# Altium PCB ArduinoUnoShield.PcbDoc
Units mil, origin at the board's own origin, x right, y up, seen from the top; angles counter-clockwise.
Board outline 2700 x 2100 mil, 2 copper layers (Top Layer, Bottom Layer); 5 components, 32 nets, 42 pads, 0 vias.
Unrouted connection lines stored in the file: 5.
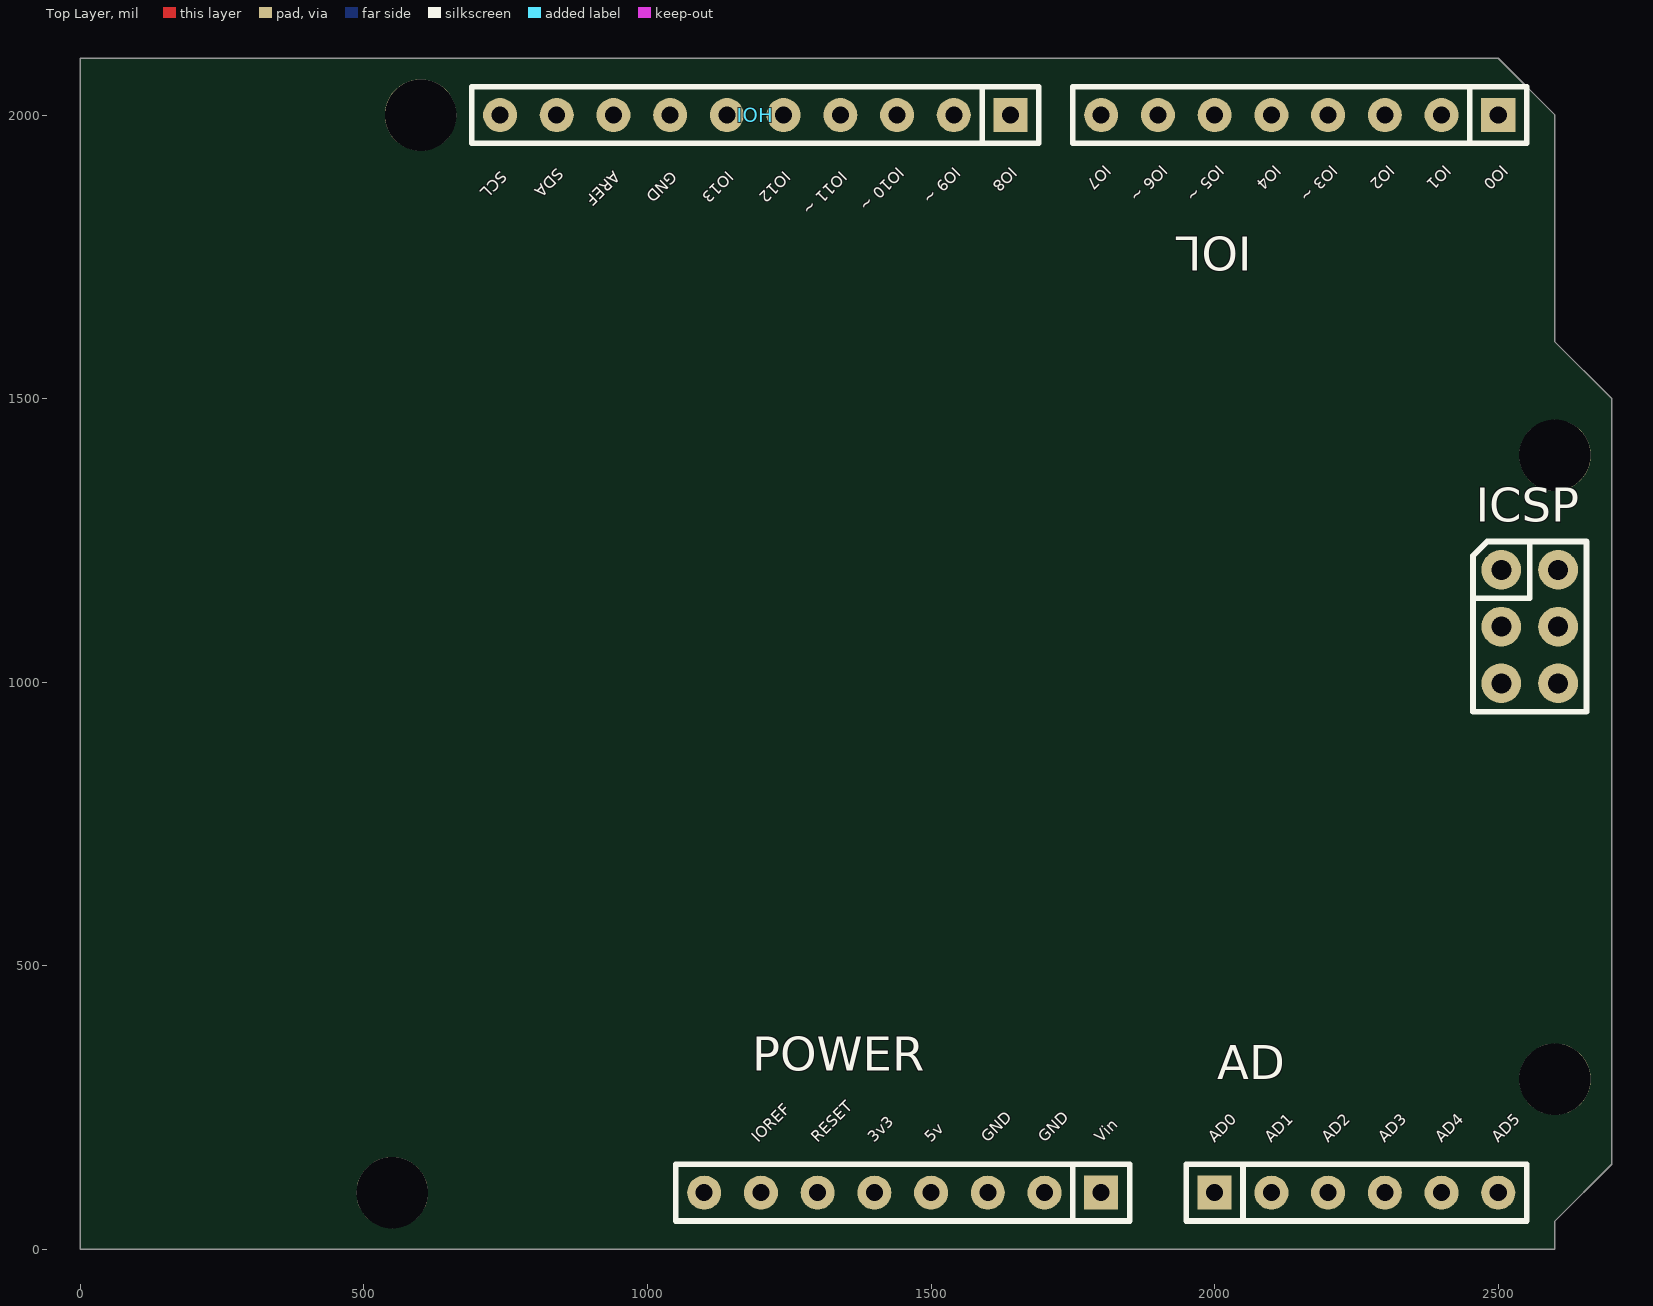
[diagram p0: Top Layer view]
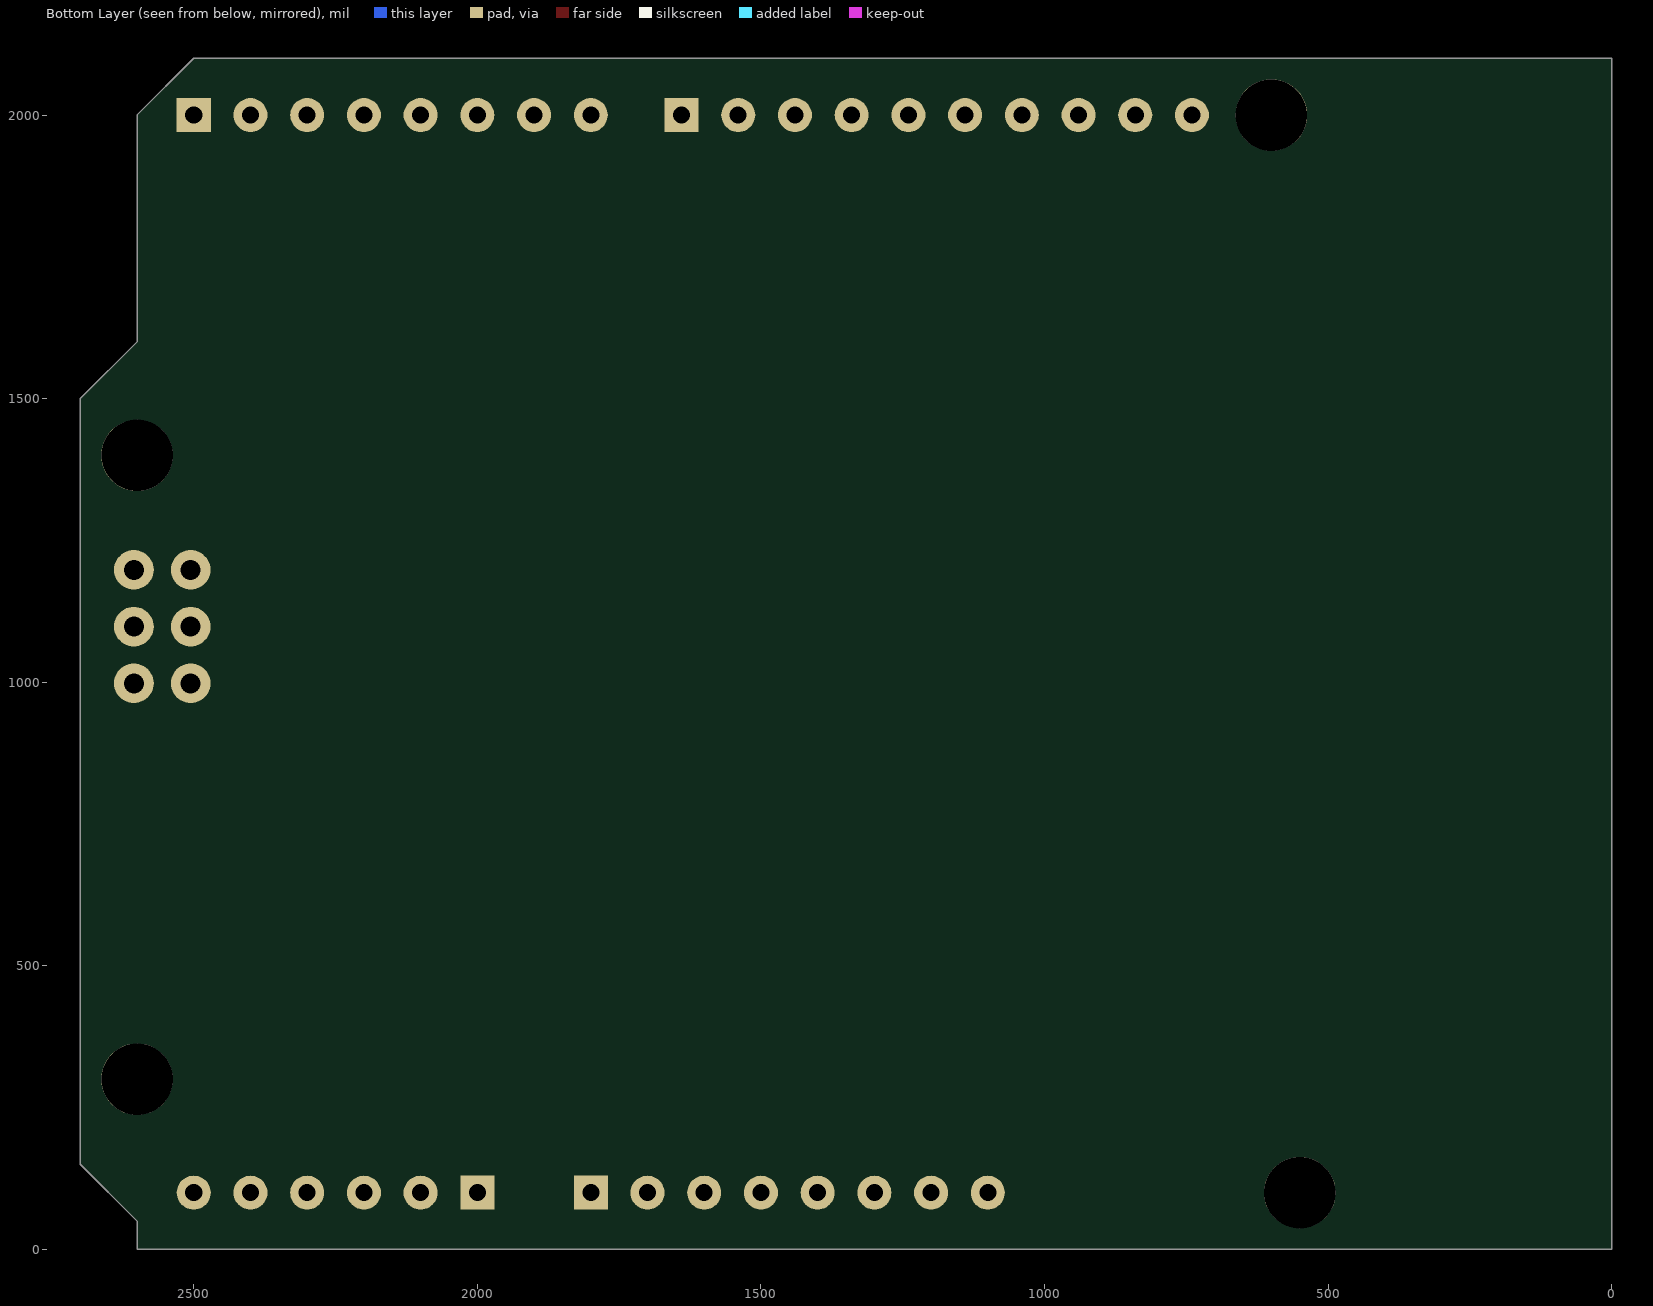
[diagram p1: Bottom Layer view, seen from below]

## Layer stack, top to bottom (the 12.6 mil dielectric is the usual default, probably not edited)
Top Layer: signal copper 1.4
Dielectric: dielectric 12.6, FR-4, Dk 4.8
Bottom Layer: signal copper 1.4

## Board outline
0,0 0,2100 2500,2100 2600,2000 2600,1600 2700,1500 2700,150 2600,50 2600,0

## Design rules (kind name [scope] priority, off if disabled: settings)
Clearance [All] p1: gap=10
PolygonConnect [All] p1: connectstyle=Relief reliefconductorwidth=10 reliefentries=4 polygonreliefangle="90 Angle" airgapwidth=10
RoomDefinition ArduinoUnoShield [InComponentClass('ArduinoUnoShield')] p1: confinementstyle=ConfineOut formatcopy=TRUE lockcomponents=FALSE outline 2745,-35 3335,-35 3335,430 2745,430
RoutingVias [All] p1: holewidth=28 width=50 viastyle="Through Hole" minholewidth=28 minwidth=50 maxholewidth=28 maxwidth=50
SilkscreenOverComponentPads [All] p1: minsilkscreentomaskgap=10
SolderMaskExpansion [All] p1: expansion=4
Width [All] p1: maxlimit=10 minlimit=10 preferedwidth=10
27 further rules are at their usual default settings.

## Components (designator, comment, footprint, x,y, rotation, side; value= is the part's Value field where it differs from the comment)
AD "AD" "Header 6x1 8.5mm" 2000,100 r0 top locked
ICSP "ICSP" ICSP 2505.51,1198.03 r0 top locked
IOH "IOH" "Header 10x1 8.5mm" 1640,2000 r180 top locked
IOL "IOL" "Header 8x1 8.5mm" 2500,2000 r180 top locked
POWER "POWER_UNO" "Header 8x1 8.5mm" 1800,100 r180 top locked

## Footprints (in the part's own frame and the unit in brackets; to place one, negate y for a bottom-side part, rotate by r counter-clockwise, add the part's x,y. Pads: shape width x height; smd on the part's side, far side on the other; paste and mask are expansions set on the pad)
"Header 6x1 8.5mm" [mil] "Stackable 6 pin header"
  rect 60x60 hole 30: 1(0,0)
  round 60 hole 30: 2(100,0) 3(200,0) 4(300,0) 5(400,0) 6(500,0)
  silkscreen extent -50,-50 550,50, body extent -50,-50 550,50, height 335
"Header 8x1 8.5mm" [mil] "Stackable 8 pin header"
  rect 60x60 hole 30: 1(0,0)
  round 60 hole 30: 2(100,0) 3(200,0) 4(300,0) 5(400,0) 6(500,0) 7(600,0) 8(700,0)
  silkscreen extent -50,-50 750,50, body extent -50,-50 750,50, height 335
"Header 10x1 8.5mm" [mil] "Stackable 10 pin header"
  rect 60x60 hole 30: 1(0,0)
  round 60 hole 30: 2(100,0) 3(200,0) 4(300,0) 5(400,0) 6(500,0) 7(600,0) 8(700,0) 9(800,0) 10(900,0)
  silkscreen extent -50,-50 950,50, body extent -50,-50 950,50, height 335
ICSP [mil]
  round 70 hole 35.43: 1(0,0) 2(100,0) 3(0,-100) 4(100,-100) 5(0,-200) 6(100,-200)
  silkscreen extent -50,-250 150,50, body extent -50,-250 150,50, height 485

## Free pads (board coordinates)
  round 125.98 hole 125.98: 0(550,100) 0(600,2000) 0(2600,300) 0(2600,1400)

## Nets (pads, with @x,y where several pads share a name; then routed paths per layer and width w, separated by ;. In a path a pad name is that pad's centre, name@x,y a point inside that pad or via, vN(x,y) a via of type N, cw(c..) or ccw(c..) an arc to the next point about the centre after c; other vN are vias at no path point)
3V3: POWER.5
5V: ICSP.2 POWER.4
AD0: AD.1
AD1: AD.2
AD2: AD.3
AD3: AD.4
AD4: AD.5
AD5: AD.6
AREF: IOH.8
GND: ICSP.6 IOH.7 POWER.2 POWER.3
IO0: IOL.1
IO1: IOL.2
IO2: IOL.3
IO3: IOL.4
IO4: IOL.5
IO5: IOL.6
IO6: IOL.7
IO7: IOL.8
IO8: IOH.1
IO9: IOH.2
IO10: IOH.3
IO11: IOH.4
IO12: IOH.5
IO13: IOH.6
IOREF: POWER.7
MISO: ICSP.1
MOSI: ICSP.4
RESET: ICSP.5 POWER.6
SCK: ICSP.3
SCL: IOH.10
SDA: IOH.9
VIN: POWER.1
pads on no net: POWER.8

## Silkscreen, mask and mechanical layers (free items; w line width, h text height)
Top Overlay:
  text "IO7" at 1805,1912.93 h20 r225
  text "IO6 ~" at 1905,1912.93 h20 r225
  text "IO5 ~" at 2005,1912.93 h20 r225
  text "IO4" at 2105,1912.93 h20 r225
  text "IO3 ~" at 2205,1912.93 h20 r225
  text "IO2" at 2305,1912.93 h20 r225
  text "IO1" at 2405,1912.93 h20 r225
  text "IO0" at 2505,1912.93 h20 r225
  text "IO10 ~" at 1440,1910 h20 r225
  text "IO9 ~" at 1540,1910 h20 r225
  text "IO8" at 1640,1910 h20 r225
  text "SDA" at 840,1907.93 h20 r225
  text "SCL" at 740,1902.93 h20 r225
  text "AREF" at 940,1902.93 h20 r225
  text "GND" at 1040,1902.93 h20 r225
  text "IO13" at 1140,1902.93 h20 r225
  text "IO12" at 1240,1902.93 h20 r225
  text "IO11 ~" at 1340,1902.93 h20 r225
  text "IOREF" at 1195,187.07 h20 r45
  text "RESET" at 1300,187.07 h20 r45
  text "3v3" at 1400,187.07 h20 r45
  text "5v" at 1500,187.07 h20 r45
  text "GND" at 1600,187.07 h20 r45
  text "GND" at 1700,187.07 h20 r45
  text "Vin" at 1800,187.07 h20 r45
  text "AD0" at 2000,187.07 h20 r45
  text "AD1" at 2100,187.07 h20 r45
  text "AD2" at 2200,187.07 h20 r45
  text "AD3" at 2300,187.07 h20 r45
  text "AD4" at 2400,187.07 h20 r45
  text "AD5" at 2500,187.07 h20 r45
  text "RESET" at 1295,-2515 h20 r45
  text "3v3" at 1395,-2515 h20 r45
  text "5v" at 1495,-2515 h20 r45
  text "GND" at 1595,-2515 h20 r45
  text "GND" at 1695,-2515 h20 r45
  text "Vin" at 1795,-2515 h20 r45
Mechanical 1:
  circle w5: c600,2000 r62.99
  circle w5: c2600,300 r62.99
  circle w5: c550,100 r62.99
  circle w5: c2600,1400 r62.99
  lines w5: 0,0 0,2100 2500,2100 2600,2000 2600,1600 2700,1500 2700,150 2600,50 2600,0 0,0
